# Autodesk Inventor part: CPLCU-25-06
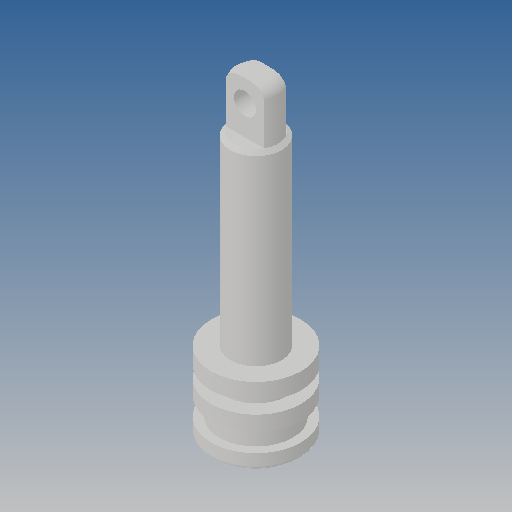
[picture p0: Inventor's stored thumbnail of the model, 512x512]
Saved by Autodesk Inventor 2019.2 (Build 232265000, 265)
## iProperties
Created: 2010-03
Part Number: CPLCU-25-06
Material: Ogólny
Document SubType Name: Modeling
Designer: CADENGINEERING4
Density: 1 g/cm^3
Appearance: Domyślna
Author: CADENGINEERING4
Revision Number: 1LAST_VERSION
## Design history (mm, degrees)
feature "Baza1"
node "Bryła1"
